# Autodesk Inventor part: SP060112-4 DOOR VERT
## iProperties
Created: 2012-06
Part Number: SP060112-4 DOOR VERT
Material: Aluminum-6061
Description: PROFILE 45X45 UL
Document SubType Name: Modeling
Designer: Administrator
Stock Number: 20.1063 PROFILE 45X45 UL
Density: 2.71 g/cm^3
FINISH: CLEAR ANODIZED
Author: Administrator
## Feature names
1. Extrusion1
